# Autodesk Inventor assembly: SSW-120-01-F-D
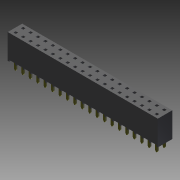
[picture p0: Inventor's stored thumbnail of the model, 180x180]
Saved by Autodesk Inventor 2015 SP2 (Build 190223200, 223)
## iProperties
Category: PARTsolutions
Company: SAMTEC
Created: 2015-08
Part Number: SSW-120-01-F-D
Catalog Web Link: www.cadenas.de
Description: SSW Series-SSW Series - (2,54 mm) .100" Surface Mount Terminal & Through-Hole .025" Square Post Socket
Vendor: SAMTEC
Document SubType Name: Assembly
Designer: PARTuser1
Manufacturer: SAMTEC
Mass: 1.92861 g
Surface Area: 31.8981 cm^2
Volume: 1.92861 cm^3
Density: 1 g/cm^3
PSOL_IDENT_0: {$CADENAS_DATA\23d-libs\samtec\modelling\ssw\ssw_asmtab.prj},243 {VTYP=3D},{STYP=ASSTAB},{NB=SSW-120
PSOL_IDENT_1: -01-F-D},{LINA=SSW-120-01-F-D},{NN=SSW Series},{DATE=15.05.2015 12:28:12},{GEOMDATE=11.11.2014 08:00
PSOL_IDENT_2: :37},{VERSION=},{LINEID=10},{LINESUBID=-1},{WBVAR=POS,LS,PLOPT,ROW,TOPT,POLOPT,NOPT,LLOPT,POPT,KOPT,
PSOL_IDENT_3: TROPT}  {NB=SSW-120-01-F-D},{LINA=SSW-120-01-F-D},{KT=DUMMY},{PN=SSW-120-01-F-D},{SERIES=SSW},{POS=2
PSOL_IDENT_4: 0},{POSATOF=20},{LS=01},{LSALG= '01','-01','02','-02','03','-03','04','-04','06','-06','21','-21','2
PSOL_IDENT_5: 2','-22','23','-23','24','-24' },{PLOPT=F},{PLOPTALG= 'G','-G - Gold, 20micro\" Au / 50micro\" Ni Mi
PSOL_IDENT_6: n on Contact, 3micro\" Au / 50micro\" Ni Min on Tail','S','-S - Selective, 30micro\" Au / 50micro\"
PSOL_IDENT_7: Ni Min on Contact, Matte Tin Tail (Non-standard option -  Please contact SAMTEC)','H','-H - Heavy Go
PSOL_IDENT_8: ld 30micro\" Au / 50micro\" Ni Min on Contact, 3micro\" Au / 50micro\" Ni Min on Tail (Non-standard
PSOL_IDENT_9: option -  Please contact SAMTEC)' ,'F','-F - Flash Selective, 3micro\" Au / 50micro\" Ni Min on Cont
PSOL_IDENT_10: act, Matte Tin Tail','STL','-STL - Selective, 30micro\" Au / 50micro\" Ni Min on Contact Area, Tin/L
PSOL_IDENT_11: ead (90/10 +/-5%) Tail (Non-standard option -  Please contact SAMTEC)','SM','-SM - Selective, 30micr
PSOL_IDENT_12: o\" Au / 50micro\" Ni Min on Contact, Matte Tin Tail (Non-standard option -  Please contact SAMTEC)'
PSOL_IDENT_13: ,'FM','-FM - Flash Selective, 3micro\" Au / 50micro\" Ni Min on Contact, Matte Tin Tail (Non-standar
PSOL_IDENT_14: d option -  Please contact SAMTEC)','L','-L - Light Selective, 10micro\" Au / 50micro\" Ni Min on Co
PSOL_IDENT_15: ntact Area, Matte Tin Tail','T','-T - Matte Tin Contact and Tail','E','-E - 50micro\" Extra Heavy Go
PSOL_IDENT_16: ld in Contact Area, 3micro\" Gold on Tail (Non-standard option -  Please contact SAMTEC)','TL','-TL
PSOL_IDENT_17: - Tin/Lead (90/10 ± 5%) Contact and Tail (Non-standard option -  Please contact SAMTEC)','TM','-TM -
PSOL_IDENT_18: Matte Tin Contact and Tail (Non-standard option -  Please contact SAMTEC)' },{ROW=D},{ROWALG= 'S','
PSOL_IDENT_19: -S - Single', 'P','-P - Single Notched','D','-D - Double','T','-T - Triple','Q','-Q - Triple with on
PSOL_IDENT_20: ly Outer 2 Rows Filled' },{TOPT=},{TOPTALG= '','Straight' },{TOPTPN=},{POLOPT=},{POLOPTALG= '','Not
PSOL_IDENT_21: Selected','001','001','002','002','003','003','004','004','005','005','006','006','007','007','008','
PSOL_IDENT_22: 008','009','009','010','010','011','011','012','012','013','013','014','014','015','015','016','016'
PSOL_IDENT_23: ,'017','017','018','018','019','019','020','020','021','021','022','022','023','023','024','024','02
PSOL_IDENT_24: 5','025','026','026','027','027','028','028','029','029','030','030','031','031','032','032','033','
PSOL_IDENT_25: 033','034','034','035','035','036','036','037','037','038','038','039','039','040','040' },{POLOPTMA
PSOL_IDENT_26: X=480},{POLOPTMAX2='001','001','002','002','003','003','004','004','005','005','006','006','007','00
PSOL_IDENT_27: 7','008','008','009','009','010','010','011','011','012','012','013','013','014','014','015','015','
PSOL_IDENT_28: 016','016','017','017','018','018','019','019','020','020','021','021','022','022','023','023','024'
PSOL_IDENT_29: ,'024','025','025','026','026','027','027','028','028','029','029','030','030','031','031','032','03
PSOL_IDENT_30: 2','033','033','034','034','035','035','036','036','037','037','038','038','039','039','040','040'},
PSOL_IDENT_31: {POLARIZE='001','001','002','002','003','003','004','004','005','005','006','006','007','007','008','
PSOL_IDENT_32: 008','009','009','010','010','011','011','012','012','013','013','014','014','015','015','016','016'
PSOL_IDENT_33: ,'017','017','018','018','019','019','020','020','021','021','022','022','023','023','024','024','02
PSOL_IDENT_34: 5','025','026','026','027','027','028','028','029','029','030','030','031','031','032','032','033','
PSOL_IDENT_35: 033','034','034','035','035','036','036','037','037','038','038','039','039','040','040','041','041'
PSOL_IDENT_36: ,'042','042','043','043','044','044','045','045','046','046','047','047','048','048','049','049','05
PSOL_IDENT_37: 0','050','051','051','052','052','053','053','054','054','055','055','056','056','057','057','058','
PSOL_IDENT_38: 058','059','059','060','060','061','061','062','062','063','063','064','064','065','065','066','066'
PSOL_IDENT_39: ,'067','067','068','068','069','069','070','070','071','071','072','072','073','073','074','074','07
PSOL_IDENT_40: 5','075','076','076','077','077','078','078','079','079','080','080','081','081','082','082','083','
PSOL_IDENT_41: 083','084','084','085','085','086','086','087','087','088','088','089','089','090','090','091','091'
PSOL_IDENT_42: ,'092','092','093','093','094','094','095','095','096','096','097','097','098','098','099','099','10
PSOL_IDENT_43: 0','100','101','101','102','102','103','103','104','104','105','105','106','106','107','107','108','
PSOL_IDENT_44: 108','109','109','110','110','111','111','112','112','113','113','114','114','115','115','116','116'
PSOL_IDENT_45: ,'117','117','118','118','119','119','120','120','121','121','122','122','123','123','124','124','12
PSOL_IDENT_46: 5','125','126','126','127','127','128','128','129','129','130','130','131','131','132','132','133','
PSOL_IDENT_47: 133','134','134','135','135','136','136','137','137','138','138','139','139','140','140','141','141'
PSOL_IDENT_48: ,'142','142','143','143','144','144','145','145','146','146','147','147','148','148','149','149','15
PSOL_IDENT_49: 0','150'},{POLOPTPN=},{NOPT=},{NOPTALG= '','Not Selected','N','-N - Notch (Non-standard option -  Pl
PSOL_IDENT_50: ease contact SAMTEC)' },{NOPTPN=},{LLOPT=},{LLOPTALG= '','Not Selected','LL','-LL - Locking Lead' },
PSOL_IDENT_51: {LLOPTPN=},{POPT=},{POPTALG= '','Not Available' },{POPTPN=},{KOPT=},{KOPTALG= '','Not Available' },{
PSOL_IDENT_52: KOPTPN=},{TROPT=},{TROPTALG= '','Not Available' },{TROPTPN=},{PPATH=parts/ssw_asmtpl.prj}
NN: SSW Series
NT: SSW Series - (2,54 mm) .100" Surface Mount Terminal & Through-Hole .025" Square Post Socket
NB: SSW-120-01-F-D
NBSYN: $PN.
LINA: SSW-120-01-F-D
PN: SSW-120-01-F-D
SERIES: SSW
POS: -20
LS: -01
PLOPT: -F - Flash Selective, 3micro" Au / 50micro" Ni Min on Contact, Matte Tin Tail
ROW: -D - Double
TOPT: Straight
POLOPT: Not Selected
NOPT: Not Selected
LLOPT: Not Selected
POPT: Not Available
KOPT: Not Available
TROPT: Not Available
SUPPLIER: SAMTEC
ARTICLENO: SSW-120-01-F-D
BOMINFO: SSW-120-01-F-D
CREATOR: CADENAS GmbH
Title: SSW-120-01-F-D
Author: Cadenas PARTsolutions
Comments: SSW Series - (2,54 mm) .100" Surface Mount Terminal & Through-Hole .025" Square Post Socket
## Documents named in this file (3)
- D:\Tigers SVN\mechanik\2016\Inventor\Kaufteile\SSW-120-01-F-D\SSW-120-01-F-D.iam
- D:\Tigers SVN\mechanik\2016\Inventor\Kaufteile\SSW-120-01-F-D\SSW-120-01-F-D_terminal.ipt
- D:\Tigers SVN\mechanik\2016\Inventor\Kaufteile\SSW-120-01-F-D\SSW-120-01-F-D_pin.ipt
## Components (2 placed, 2 different names)
1. SSW-120-01-F-D_terminal:1
2. SSW-120-01-F-D_pin:1
